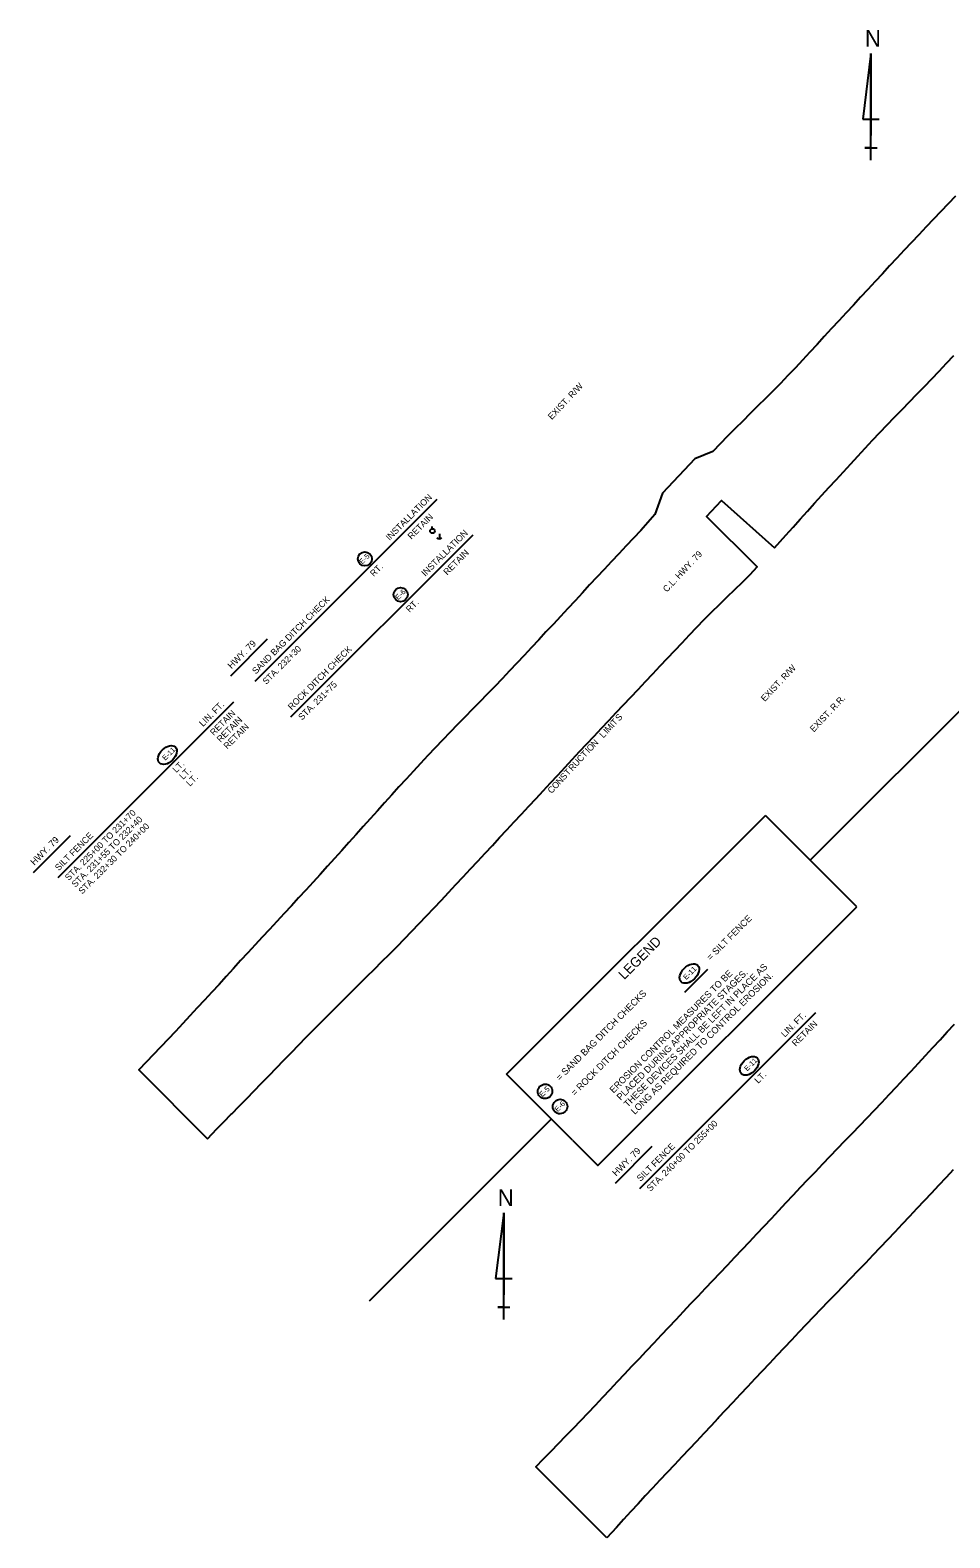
# Model space of a CAD drawing. Extents: x 1388120 to 1389841, y 1944102 to 1945760.
# Drawn here: x 1388120 to 1388980, y 1944102 to 1945514 of the extents above; entities that cross this region are included whole.
import ezdxf

# ---------------------------------------------------------------- set-up
doc = ezdxf.new("R2010")
doc.units = 0
for name, color, linetype in [('1', 7, 'Continuous'), ('44', 7, 'Continuous'), ('63', 7, 'Continuous'), ('Level 1', 7, 'Continuous'), ('Level 44', 7, 'Continuous'), ('R_Draft', 7, 'Continuous'), ('R_NO PLOT', 7, 'Continuous'), ('S_UTILITY_POLE', 7, 'Continuous')]:
    doc.layers.add(name, color=color, linetype=linetype)

msp = doc.modelspace()

# ---------------------------------------------------------------- linework, layer by layer
at = {"layer": '1'}
for p, q in [((1388849.6, 1944736.7), (1389051.9, 1944939.1)), ((1388565.3, 1944536.4), (1388807.6, 1944778.6)), ((1388893.2, 1944693.1), (1388807.6, 1944778.6)), ((1388627, 1944474.7), (1388565.3, 1944536.4)), ((1388437.2, 1944324.3), (1388607.3, 1944494.4))]:
    msp.add_line(p, q, dxfattribs=at)
msp.add_lwpolyline([(1388627, 1944474.7), (1388650.9, 1944450.8), (1388893.2, 1944693.1)], dxfattribs=at)
for centre in [(1388432.8, 1945018.8), (1388466.3, 1944985.4)]:
    msp.add_circle(centre, 6.61, dxfattribs=at)
for centre in [(1388248, 1944835.2), (1388792.6, 1944544.2)]:
    msp.add_ellipse(centre, major_axis=(7.44, 7.44), ratio=0.638788, dxfattribs=at)
at = {"layer": '44'}
for p, q in [((1388330.1, 1944904.5), (1388500.5, 1945074.9)), ((1388363.6, 1944871), (1388534, 1945041.4)), ((1388307.3, 1944909.3), (1388341.8, 1944943.9)), ((1388145.6, 1944720.4), (1388310.2, 1944885)), ((1388122.7, 1944725.3), (1388157.3, 1944759.8)), ((1388690.1, 1944429.5), (1388854.7, 1944594.1)), ((1388667.3, 1944434.3), (1388701.8, 1944468.9))]:
    msp.add_line(p, q, dxfattribs=at)
at = {"layer": '63'}
for p, q in [((1388906.4, 1945492.1), (1388898.7, 1945430.6)), ((1388906.4, 1945392.1), (1388906.4, 1945492.1)), ((1388906.4, 1945492.1), (1388906.4, 1945415.2)), ((1388898.7, 1945430.6), (1388914.1, 1945430.6)), ((1388906.4, 1945392.1), (1388906.4, 1945415.2)), ((1388906.4, 1945403.6), (1388900.6, 1945403.6)), ((1388900.6, 1945403.6), (1388912.2, 1945403.6)), ((1388906.4, 1945392.1), (1388906.4, 1945403.6)), ((1388562.8, 1944406.7), (1388555.2, 1944345.2)), ((1388562.8, 1944306.7), (1388562.8, 1944406.7)), ((1388562.8, 1944406.7), (1388562.8, 1944329.8)), ((1388555.2, 1944345.2), (1388570.5, 1944345.2)), ((1388562.8, 1944306.7), (1388562.8, 1944329.8)), ((1388562.8, 1944318.3), (1388557.1, 1944318.3)), ((1388557.1, 1944318.3), (1388568.6, 1944318.3)), ((1388562.8, 1944306.7), (1388562.8, 1944318.3))]:
    msp.add_line(p, q, dxfattribs=at)
at = {"layer": 'Level 1'}
for centre, major_axis, ratio in [((1388736.5, 1944630.6), (7.75, 7.75), 0.622952), ((1388601.4, 1944520.3), (-4.87, -4.86), 0.97521), ((1388615.5, 1944506.1), (-4.87, -4.86), 0.97521)]:
    msp.add_ellipse(centre, major_axis=major_axis, ratio=ratio, dxfattribs=at)
at = {"layer": 'Level 44'}
msp.add_lwpolyline([(1388732.4, 1944613.3), (1388753.7, 1944634.6)], dxfattribs=at)
at = {"layer": 'R_NO PLOT'}
for points in [[(1388985.7, 1945358.6), (1388978.7, 1945351.4), (1388971.8, 1945344.2), (1388964.9, 1945337), (1388958, 1945329.8), (1388951.2, 1945322.4), (1388944.4, 1945315.1), (1388937.6, 1945307.8), (1388930.8, 1945300.5), (1388923.9, 1945293.2), (1388917.1, 1945285.8), (1388910.3, 1945278.5), (1388903.5, 1945271.2), (1388896.7, 1945263.8), (1388890, 1945256.4), (1388883.2, 1945249.1), (1388876.4, 1945241.7), (1388869.6, 1945234.4), (1388862.8, 1945227.1), (1388856.1, 1945219.7), (1388849.3, 1945212.4), (1388842.5, 1945205), (1388835.8, 1945197.6), (1388828.8, 1945190.4), (1388821.9, 1945183.2), (1388814.8, 1945176.2), (1388807.7, 1945169.1), (1388800.6, 1945162), (1388793.5, 1945155), (1388786.5, 1945147.9), (1388779.4, 1945140.8), (1388772.3, 1945133.7), (1388765.4, 1945126.5), (1388758.3, 1945119.4), (1388741.5, 1945112.6), (1388711.2, 1945080.3), (1388704.3, 1945060.4), (1388697.6, 1945053), (1388691, 1945045.5), (1388684.1, 1945038.2), (1388677.2, 1945031), (1388670.4, 1945023.7), (1388663.6, 1945016.3), (1388656.8, 1945009), (1388649.9, 1945001.7), (1388643.1, 1944994.4), (1388636.4, 1944987), (1388629.6, 1944979.7), (1388622.8, 1944972.4), (1388616, 1944965), (1388609.2, 1944957.7), (1388602.3, 1944950.4), (1388595.5, 1944943.1), (1388588.6, 1944935.8), (1388581.8, 1944928.5), (1388574.9, 1944921.2), (1388568.1, 1944914), (1388561.2, 1944906.7), (1388554.3, 1944899.5), (1388547.3, 1944892.3), (1388540.4, 1944885.1), (1388533.4, 1944878), (1388526.4, 1944870.8), (1388519.4, 1944863.7), (1388512.5, 1944856.5), (1388505.6, 1944849.2), (1388498.7, 1944842), (1388491.8, 1944834.7), (1388485, 1944827.4), (1388478.2, 1944820), (1388471.5, 1944812.7), (1388464.7, 1944805.3), (1388457.9, 1944797.9), (1388451.2, 1944790.5), (1388444.5, 1944783.1), (1388437.8, 1944775.6), (1388431.2, 1944768.2), (1388424.5, 1944760.7), (1388417.8, 1944753.3), (1388411.1, 1944745.8), (1388404.5, 1944738.4), (1388397.8, 1944731), (1388391.1, 1944723.5), (1388384.4, 1944716.1), (1388377.6, 1944708.8), (1388370.8, 1944701.4), (1388364, 1944694.1), (1388357.2, 1944686.7), (1388350.4, 1944679.4), (1388343.6, 1944672), (1388336.8, 1944664.7), (1388330, 1944657.4), (1388323.2, 1944650), (1388316.5, 1944642.7), (1388309.7, 1944635.3), (1388303, 1944627.9), (1388296.3, 1944620.5), (1388289.5, 1944613.2), (1388282.7, 1944605.8), (1388275.9, 1944598.5), (1388269.1, 1944591.1), (1388262.3, 1944583.8), (1388255.5, 1944576.4), (1388248.7, 1944569.2), (1388241.8, 1944561.9), (1388241.1, 1944561.3), (1388234.9, 1944554.8), (1388221.1, 1944540.4), (1388285.5, 1944476)], [(1388816.1, 1945029.2), (1388826.9, 1945041.2), (1388833.6, 1945048.7), (1388840.2, 1945056.1), (1388847, 1945063.5), (1388853.6, 1945071), (1388860.4, 1945078.4), (1388867.1, 1945085.7), (1388873.9, 1945093), (1388880.7, 1945100.4), (1388887.5, 1945107.7), (1388894.2, 1945115.1), (1388901, 1945122.5), (1388907.8, 1945129.9), (1388914.7, 1945137.1), (1388921.6, 1945144.3), (1388928.5, 1945151.5), (1388935.5, 1945158.7), (1388942.5, 1945165.9), (1388949.5, 1945173), (1388956.4, 1945180.2), (1388963.4, 1945187.4), (1388970.2, 1945194.7), (1388977.1, 1945202), (1388983.9, 1945209.3)], [(1388285.5, 1944476), (1388294.1, 1944485.2), (1388301.2, 1944492.2), (1388307.4, 1944498.6), (1388308.2, 1944499.4), (1388315.3, 1944506.5), (1388322.3, 1944513.7), (1388329.2, 1944520.9), (1388336.1, 1944528.1), (1388343.1, 1944535.3), (1388350, 1944542.4), (1388357.1, 1944549.6), (1388364, 1944556.7), (1388371, 1944563.9), (1388378, 1944571.1), (1388385, 1944578.2), (1388392.1, 1944585.3), (1388399.1, 1944592.4), (1388406.2, 1944599.5), (1388413.3, 1944606.5), (1388420.3, 1944613.6), (1388427.5, 1944620.6), (1388434.6, 1944627.7), (1388441.7, 1944634.7), (1388448.8, 1944641.8), (1388455.9, 1944648.9), (1388462.9, 1944656), (1388469.8, 1944663.2), (1388476.8, 1944670.4), (1388483.7, 1944677.6), (1388490.6, 1944684.8), (1388497.5, 1944692.1), (1388504.4, 1944699.3), (1388511.2, 1944706.6), (1388518, 1944713.9), (1388524.9, 1944721.2), (1388531.7, 1944728.6), (1388538.5, 1944735.9), (1388545.3, 1944743.2), (1388552.1, 1944750.6), (1388558.8, 1944757.9), (1388565.6, 1944765.2), (1388572.5, 1944772.6), (1388579.3, 1944779.9), (1388586.1, 1944787.2), (1388593, 1944794.5), (1388599.8, 1944801.8), (1388606.6, 1944809.1), (1388613.4, 1944816.4), (1388620.2, 1944823.8), (1388626.9, 1944831.1), (1388633.7, 1944838.5), (1388640.6, 1944845.8), (1388647.5, 1944853), (1388654.3, 1944860.3), (1388661.2, 1944867.6), (1388668, 1944874.9), (1388674.9, 1944882.1), (1388681.8, 1944889.4), (1388688.6, 1944896.7), (1388695.4, 1944904), (1388702.2, 1944911.3), (1388709.1, 1944918.6), (1388715.9, 1944925.9), (1388722.8, 1944933.2), (1388729.7, 1944940.4), (1388736.6, 1944947.7), (1388743.5, 1944954.9), (1388750.4, 1944962.2), (1388757.4, 1944969.3), (1388764.6, 1944976.2), (1388771.8, 1944983.2), (1388779, 1944990.2), (1388786.1, 1944997.2), (1388793.3, 1945004.2), (1388800, 1945011.5), (1388752.6, 1945058.5), (1388766.6, 1945073.6), (1388816.1, 1945029.2)], [(1388659.3, 1944102.3), (1388592.9, 1944168.6), (1388600.1, 1944176.2), (1388607, 1944183.4), (1388614, 1944190.5), (1388620.9, 1944197.7), (1388627.9, 1944204.9), (1388634.8, 1944212.1), (1388641.7, 1944219.4), (1388648.6, 1944226.6), (1388655.4, 1944233.9), (1388662.3, 1944241.2), (1388669.2, 1944248.5), (1388676, 1944255.8), (1388682.8, 1944263.1), (1388689.7, 1944270.3), (1388696, 1944277.1), (1388696.6, 1944277.7), (1388703.4, 1944285), (1388710.3, 1944292.2), (1388717.2, 1944299.5), (1388724, 1944306.8), (1388730.9, 1944314.1), (1388737.7, 1944321.4), (1388744.6, 1944328.6), (1388751.5, 1944335.9), (1388758.3, 1944343.2), (1388765.2, 1944350.4), (1388772.1, 1944357.7), (1388778.9, 1944365), (1388785.8, 1944372.3), (1388792.7, 1944379.5), (1388799.6, 1944386.8), (1388806.5, 1944394), (1388813.3, 1944401.3), (1388820.1, 1944408.6), (1388826.9, 1944416), (1388833.8, 1944423.3), (1388840.6, 1944430.6), (1388847.5, 1944437.8), (1388854.4, 1944445), (1388861.3, 1944452.3), (1388868.3, 1944459.5), (1388875.2, 1944466.7), (1388882.1, 1944473.9), (1388889.1, 1944481.1), (1388896, 1944488.3), (1388903, 1944495.5), (1388909.9, 1944502.7), (1388916.7, 1944510), (1388923.5, 1944517.3), (1388930.4, 1944524.6), (1388937.2, 1944531.9), (1388944, 1944539.2), (1388950.8, 1944546.6), (1388957.5, 1944554), (1388964.3, 1944561.3), (1388971.1, 1944568.6), (1388977.9, 1944576), (1388984.7, 1944583.3)], [(1388983.5, 1944446.9), (1388976.7, 1944439.6), (1388969.8, 1944432.3), (1388963, 1944425), (1388956.1, 1944417.8), (1388949.3, 1944410.5), (1388942.4, 1944403.2), (1388935.6, 1944395.9), (1388928.7, 1944388.6), (1388921.9, 1944381.3), (1388915, 1944374), (1388908.1, 1944366.8), (1388901.2, 1944359.6), (1388894.3, 1944352.4), (1388887.3, 1944345.2), (1388880.4, 1944338), (1388873.5, 1944330.7), (1388866.5, 1944323.6), (1388859.6, 1944316.3), (1388852.6, 1944309.2), (1388845.8, 1944301.9), (1388838.8, 1944294.7), (1388832, 1944287.4), (1388825.1, 1944280.2), (1388818.2, 1944272.9), (1388811.4, 1944265.6), (1388804.5, 1944258.3), (1388797.7, 1944251), (1388790.9, 1944243.7), (1388784.1, 1944236.4), (1388777.2, 1944229.1), (1388770.4, 1944221.8), (1388763.6, 1944214.5), (1388763.2, 1944214), (1388756.8, 1944207.2), (1388750, 1944199.9), (1388743.1, 1944192.6), (1388736.3, 1944185.3), (1388729.5, 1944178), (1388722.6, 1944170.7), (1388715.7, 1944163.5), (1388708.9, 1944156.2), (1388702, 1944148.9), (1388695.2, 1944141.6), (1388688.5, 1944134.2), (1388681.7, 1944126.8), (1388675, 1944119.5), (1388668.2, 1944112.1), (1388659.3, 1944102.3)]]:
    msp.add_lwpolyline(points, dxfattribs=at)
at = {"layer": 'S_UTILITY_POLE'}
for p, q in [((1388495.9, 1945047.1), (1388495.9, 1945049.2)), ((1388502.5, 1945042.3), (1388502.5, 1945037.6))]:
    msp.add_line(p, q, dxfattribs=at)
msp.add_circle((1388496, 1945045), 2.13, dxfattribs=at)
msp.add_arc((1388502.5, 1945041), 3.41, 226.3972, 313.6028, dxfattribs=at)

# ---------------------------------------------------------------- texts
at = {"layer": '1'}
for s, p in [('E-5 ', (1388430.4, 1945013.5)), ('E-6 ', (1388464.1, 1944980.2)), ('E-11', (1388246, 1944829.8)), ('E-11', (1388790.6, 1944538.9))]:
    msp.add_text(s, height=4.8, rotation=45, dxfattribs=at).set_placement(p)
at = {"layer": '44'}
for s, height, p in [('INSTALLATION', 6, (1388455.9, 1945035.6)), ('RETAIN', 6, (1388476.4, 1945036.7)), ('INSTALLATION', 6, (1388489.3, 1945002.1)), ('RETAIN', 6, (1388509.8, 1945003.2)), ('RT.', 6, (1388441.2, 1945001.8)), ('SAND BAG DITCH CHECK', 6, (1388330.8, 1944910.5)), ('RT.', 6, (1388474.7, 1944968.3)), ('HWY. 79', 6.25, (1388308, 1944915.4)), ('STA. 232+30', 6, (1388340.5, 1944900.8)), ('ROCK DITCH CHECK', 6, (1388364.3, 1944877)), ('STA. 231+75', 6, (1388374, 1944867.4)), ('LIN. FT.', 6, (1388281.3, 1944861.4)), ('RETAIN', 6, (1388291.5, 1944853)), ('RETAIN', 6, (1388297.8, 1944846.7)), ('RETAIN', 6, (1388304.1, 1944840.3)), ('LT.', 6, (1388256.4, 1944818.2)), ('LT.', 6, (1388262.7, 1944811.9)), ('LT.', 6, (1388269.1, 1944805.5)), ('STA. 225+00 TO 231+70', 6, (1388155.6, 1944717.1)), ('STA. 231+55 TO 232+40', 6, (1388161.9, 1944710.9)), ('STA. 232+30 TO 240+00', 6, (1388168.3, 1944704.5)), ('HWY. 79', 6.25, (1388123.5, 1944731.4)), ('SILT FENCE      ', 6, (1388146.3, 1944726.4)), ('LIN. FT.', 6, (1388825.8, 1944570.5)), ('RETAIN', 6, (1388836, 1944562.1)), ('LT.', 6, (1388801, 1944527.2)), ('STA. 240+00 TO 255+00', 6, (1388700.1, 1944426.2)), ('HWY. 79', 6.25, (1388668, 1944440.4)), ('SILT FENCE      ', 6, (1388690.8, 1944435.5))]:
    msp.add_text(s, height=height, rotation=45, dxfattribs=at).set_placement(p)
at = {"layer": '63'}
for p in [(1388900.8, 1945498.5), (1388557.2, 1944413.1)]:
    msp.add_text('N', height=15.4, rotation=360, dxfattribs=at).set_placement(p)
at = {"layer": 'Level 1'}
for s, height, p in [('= SILT FENCE', 6.25, (1388756.4, 1944642.4)), ('THESE DEVICES SHALL BE LEFT IN PLACE AS ', 6.25, (1388678.8, 1944504.9)), ('EROSION CONTROL MEASURES TO BE', 6.25, (1388665.5, 1944518.2)), ('PLACED DURING APPROPRIATE STAGES. ', 6.25, (1388672.2, 1944511.5)), ('LONG AS REQUIRED TO CONTROL EROSION.', 6.25, (1388685.5, 1944498.2)), ('E-11 ', 4.88, (1388733.6, 1944624.4)), ('= SAND BAG DITCH CHECKS', 6.25, (1388615.3, 1944529.8)), ('= ROCK DITCH CHECKS', 6.25, (1388629.4, 1944515.6)), ('E-5 ', 4.88, (1388598.9, 1944514.7)), ('E-6 ', 4.88, (1388613.2, 1944500.8))]:
    msp.add_text(s, height=height, rotation=45, dxfattribs=at).set_placement(p)
at = {"layer": 'Level 44'}
msp.add_text('LEGEND', height=9.14, rotation=45, dxfattribs=at).set_placement((1388675.5, 1944624.3))
at = {"layer": 'R_Draft'}
for s, rotation, p in [('EXIST. R/W', 46.6607, (1388607.8, 1945148.7)), ('C.L. HWY. 79', 46.736, (1388715.4, 1944987.2)), ('EXIST. R/W', 46.6607, (1388807.1, 1944884.8)), ('EXIST. R.R.', 46.6607, (1388853, 1944856.2)), ('M', 46.702, (1388661, 1944856.1)), ('I', 46.6979, (1388665.5, 1944860.8)), ('T', 46.6979, (1388666.8, 1944862.2)), ('S', 46.6979, (1388670.8, 1944866.5)), ('N', 46.674, (1388648, 1944842.2)), ('L', 46.6927, (1388656, 1944850.7)), ('I', 46.702, (1388659.7, 1944854.6)), ('C', 47.2261, (1388634.8, 1944828.1)), ('T', 46.6953, (1388638.6, 1944832.3)), ('I', 46.6953, (1388642.6, 1944836.5)), ('O', 46.6953, (1388644, 1944838)), ('T', 47.1885, (1388623.1, 1944815.4)), ('R', 47.5187, (1388627.1, 1944819.7)), ('U', 47.2261, (1388630.9, 1944823.9)), ('C', 47.1051, (1388607.5, 1944798.6)), ('O', 47.099, (1388611.4, 1944802.8)), ('N', 47.099, (1388615.4, 1944807.1)), ('S', 47.1885, (1388619.2, 1944811.2))]:
    msp.add_text(s, height=6, rotation=rotation, dxfattribs=at).set_placement(p)

doc.saveas('drawing.dxf')
